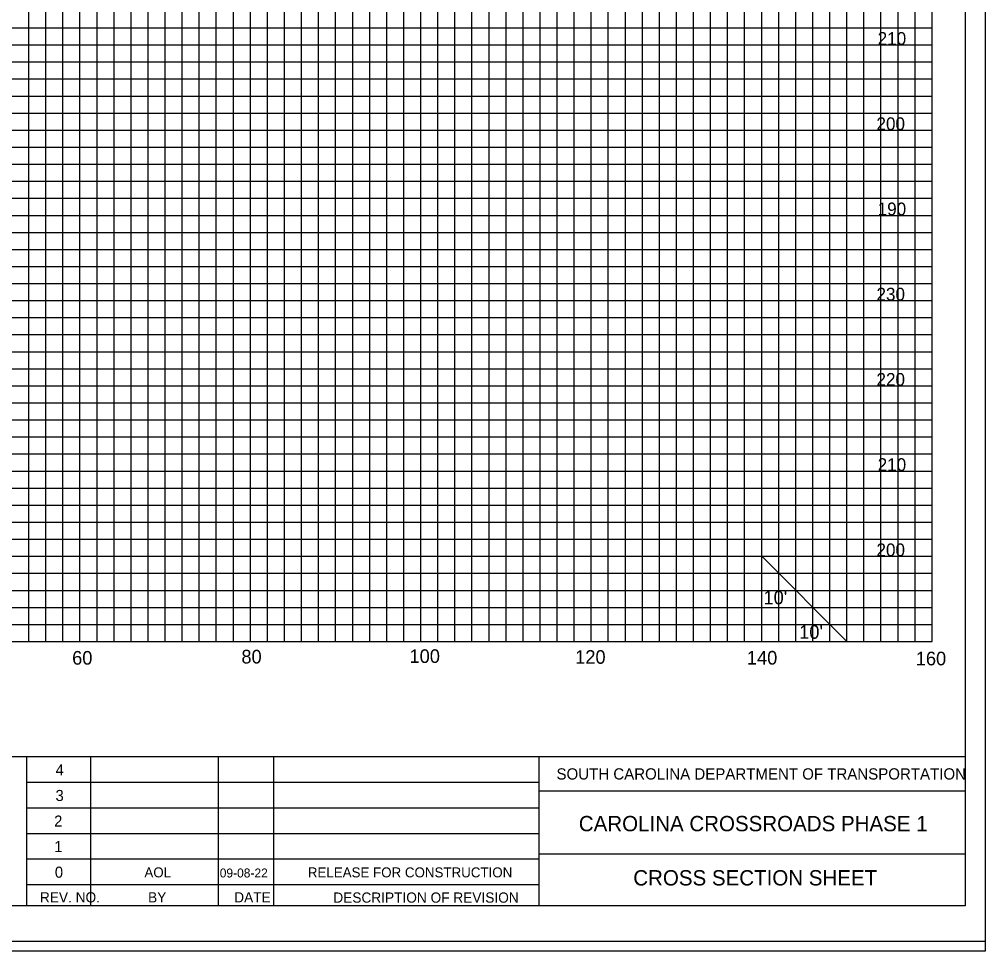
# Model space of a CAD drawing. Extents: x 967 to 1326, y 964 to 2304.
# Drawn here: x 1212.9 to 1326.3, y 1243.7 to 1353 of the extents above; entities that cross this region are included whole.
import ezdxf

# ---------------------------------------------------------------- set-up
doc = ezdxf.new("R2010")
doc.units = 0
for name, color, linetype in [('Default', 7, 'Continuous'), ('RD_GPK_XS_Cell', 7, 'Continuous'), ('RD_PD_PaveShd', 7, 'Continuous'), ('RD_XS_ExGround', 7, 'Continuous'), ('RD_XS_ExPaveRet', 7, 'Continuous'), ('RD_XS_Misc_Line', 7, 'Continuous'), ('RD_XS_PaveOvlay', 7, 'Continuous'), ('RD_XS_TX_Elev_EX', 7, 'Continuous')]:
    doc.layers.add(name, color=color, linetype=linetype)

msp = doc.modelspace()

# ---------------------------------------------------------------- linework, layer by layer
at = {"layer": 'RD_GPK_XS_Cell'}
for p, q in [((1220, 1280), (1220, 1450)), ((1230, 1280), (1230, 1450)), ((1240, 1280), (1240, 1450)), ((1250, 1280), (1250, 1450)), ((1260, 1280), (1260, 1450)), ((1270, 1280), (1270, 1450)), ((1280, 1280), (1280, 1450)), ((1290, 1280), (1290, 1450)), ((1300, 1280), (1300, 1450)), ((1310, 1280), (1310, 1450)), ((1320, 1280), (1320, 1450)), ((1000, 1350), (1320, 1350)), ((1000, 1340), (1320, 1340)), ((1000, 1330), (1320, 1330)), ((1000, 1320), (1320, 1320)), ((1000, 1310), (1320, 1310)), ((1000, 1300), (1320, 1300)), ((1000, 1290), (1320, 1290)), ((1000, 1280), (1320, 1280))]:
    msp.add_line(p, q, dxfattribs=at)
at = {"layer": 'RD_PD_PaveShd'}
for p, q in [((1323.89, 1458.46), (1323.89, 1248.98)), ((996.11, 1266.49), (1323.89, 1266.49)), ((1213.76, 1248.94), (1213.76, 1266.49)), ((1221.26, 1248.95), (1221.26, 1266.48)), ((1236.26, 1248.95), (1236.26, 1266.48)), ((1242.76, 1248.95), (1242.76, 1266.48)), ((1273.88, 1248.98), (1273.88, 1266.49)), ((1213.76, 1263.48), (1273.88, 1263.48)), ((1323.93, 1262.43), (1273.88, 1262.43)), ((1213.76, 1260.48), (1273.88, 1260.48)), ((1213.76, 1257.48), (1273.88, 1257.48)), ((1213.76, 1254.48), (1273.88, 1254.48)), ((1323.89, 1255.04), (1273.88, 1255.04)), ((1213.76, 1251.48), (1273.88, 1251.48)), ((1323.89, 1248.98), (996.11, 1248.98))]:
    msp.add_line(p, q, dxfattribs=at)
at = {"layer": 'RD_XS_ExGround'}
for p, q in [((1214, 1280), (1214, 1450)), ((1216, 1280), (1216, 1450)), ((1218, 1280), (1218, 1450)), ((1222, 1280), (1222, 1450)), ((1224, 1280), (1224, 1450)), ((1226, 1280), (1226, 1450)), ((1228, 1280), (1228, 1450)), ((1232, 1280), (1232, 1450)), ((1234, 1280), (1234, 1450)), ((1236, 1280), (1236, 1450)), ((1238, 1280), (1238, 1450)), ((1242, 1280), (1242, 1450)), ((1244, 1280), (1244, 1450)), ((1246, 1280), (1246, 1450)), ((1248, 1280), (1248, 1450)), ((1252, 1280), (1252, 1450)), ((1254, 1280), (1254, 1450)), ((1256, 1280), (1256, 1450)), ((1258, 1280), (1258, 1450)), ((1262, 1280), (1262, 1450)), ((1264, 1280), (1264, 1450)), ((1266, 1280), (1266, 1450)), ((1268, 1280), (1268, 1450)), ((1272, 1280), (1272, 1450)), ((1274, 1280), (1274, 1450)), ((1276, 1280), (1276, 1450)), ((1278, 1280), (1278, 1450)), ((1282, 1280), (1282, 1450)), ((1284, 1280), (1284, 1450)), ((1286, 1280), (1286, 1450)), ((1288, 1280), (1288, 1450)), ((1292, 1280), (1292, 1450)), ((1294, 1280), (1294, 1450)), ((1296, 1280), (1296, 1450)), ((1298, 1280), (1298, 1450)), ((1302, 1280), (1302, 1450)), ((1304, 1280), (1304, 1450)), ((1306, 1280), (1306, 1450)), ((1308, 1280), (1308, 1450)), ((1312, 1280), (1312, 1450)), ((1314, 1280), (1314, 1450)), ((1316, 1280), (1316, 1450)), ((1318, 1280), (1318, 1450)), ((1000, 1352), (1320, 1352)), ((1000, 1348), (1320, 1348)), ((1000, 1346), (1320, 1346)), ((1000, 1344), (1320, 1344)), ((1000, 1342), (1320, 1342)), ((1000, 1338), (1320, 1338)), ((1000, 1336), (1320, 1336)), ((1000, 1334), (1320, 1334)), ((1000, 1332), (1320, 1332)), ((1000, 1328), (1320, 1328)), ((1000, 1326), (1320, 1326)), ((1000, 1324), (1320, 1324)), ((1000, 1322), (1320, 1322)), ((1000, 1318), (1320, 1318)), ((1000, 1316), (1320, 1316)), ((1000, 1314), (1320, 1314)), ((1000, 1312), (1320, 1312)), ((1000, 1308), (1320, 1308)), ((1000, 1306), (1320, 1306)), ((1000, 1304), (1320, 1304)), ((1000, 1302), (1320, 1302)), ((1000, 1298), (1320, 1298)), ((1000, 1296), (1320, 1296)), ((1000, 1294), (1320, 1294)), ((1000, 1292), (1320, 1292)), ((1000, 1288), (1320, 1288)), ((1000, 1286), (1320, 1286)), ((1000, 1284), (1320, 1284)), ((1000, 1282), (1320, 1282))]:
    msp.add_line(p, q, dxfattribs=at)
at = {"layer": 'RD_XS_ExPaveRet'}
msp.add_line((1300, 1290), (1310, 1280), dxfattribs=at)
at = {"layer": 'RD_XS_PaveOvlay'}
msp.add_lwpolyline([(967.41, 1243.72), (1326.28, 1243.72), (1326.28, 1463.72), (967.41, 1463.72)], close=True, dxfattribs=at)
at = {"layer": 'RD_XS_TX_Elev_EX'}
for points in [[(967.41, 1243.72), (1326.28, 1243.72), (1326.28, 1463.72), (967.41, 1463.72)], [(988.52, 1244.84), (1326.28, 1244.84), (1326.28, 1462.6), (988.52, 1462.6)]]:
    msp.add_lwpolyline(points, close=True, dxfattribs=at)

# ---------------------------------------------------------------- texts
at = {"layer": 'Default'}
for s, p in [('210', (1313.61, 1350)), ('200', (1313.47, 1340)), ('190', (1313.61, 1330)), ('230', (1313.47, 1320)), ('220', (1313.47, 1310)), ('210', (1313.61, 1300)), ('200', (1313.47, 1290))]:
    msp.add_text(s, height=1.5, dxfattribs=at).set_placement(p)
at = {"layer": 'RD_XS_ExPaveRet'}
for s, height, p in [("10'", 1.6, (1300.21, 1284.36)), ("10'", 1.6, (1304.4, 1280.32)), ('60', 1.6, (1219.08, 1277.28)), ('80', 1.6, (1238.94, 1277.42)), ('100', 1.6, (1258.67, 1277.48)), ('120', 1.6, (1278.11, 1277.38)), ('140', 1.6, (1298.26, 1277.29)), ('160', 1.6, (1318.08, 1277.2)), ('4', 1.3, (1217.13, 1264.28)), ('SOUTH CAROLINA DEPARTMENT OF TRANSPORTATION', 1.32, (1275.92, 1263.8)), ('3', 1.3, (1217.13, 1261.28)), ('2', 1.3, (1216.97, 1258.28)), ('1', 1.3, (1216.97, 1255.28)), ('0', 1.3, (1217.05, 1252.28)), ('REV. NO.', 1.2, (1215.3, 1249.38)), ('BY', 1.2, (1227.99, 1249.38)), ('DATE', 1.2, (1238.1, 1249.38)), ('DESCRIPTION OF REVISION', 1.2, (1249.73, 1249.35))]:
    msp.add_text(s, height=height, dxfattribs=at).set_placement(p)
for s, p in [('CAROLINA CROSSROADS PHASE 1', (1278.54, 1257.73)), ('CROSS SECTION SHEET', (1284.93, 1251.37))]:
    msp.add_text(s, height=1.8, rotation=0, dxfattribs=at).set_placement(p)
at = {"layer": 'RD_XS_Misc_Line'}
for s, height, p in [('AOL', 1.17, (1227.56, 1252.32)), ('09-08-22', 1.053, (1236.4, 1252.31)), ('RELEASE FOR CONSTRUCTION', 1.17, (1246.74, 1252.32))]:
    msp.add_text(s, height=height, dxfattribs=at).set_placement(p)

doc.saveas('drawing.dxf')
